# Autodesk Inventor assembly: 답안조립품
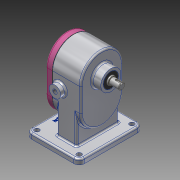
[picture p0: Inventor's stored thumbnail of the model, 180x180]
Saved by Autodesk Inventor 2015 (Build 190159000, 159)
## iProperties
Created: 2020-09
Part Number: 답안조립품
Document SubType Name: Assembly
Designer: LINEART-A501
Author: LINEART-A501
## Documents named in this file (11)
- C:\Users\LINEART-A501\Desktop\700906V1024\답안조립품.iam
- C:\Users\LINEART-A501\Desktop\700906V1024\본체.ipt
- C:\Users\LINEART-A501\Desktop\700906V1024\커버.ipt
- C:\Users\LINEART-A501\Desktop\700906V1024\베어링부시.ipt
- C:\Users\LINEART-A501\Desktop\700906V1024\개스킷.ipt
- C:\Users\LINEART-A501\Desktop\700906V1024\메인축.ipt
- C:\Users\LINEART-A501\Desktop\700906V1024\오일 실 16 28 7.ipt
- C:\Users\LINEART-A501\Desktop\700906V1024\서브축.ipt
- C:\Users\LINEART-A501\Desktop\700906V1024\키 6 x 6 x 18.ipt
- C:\Users\LINEART-A501\Desktop\700906V1024\볼트 M5.ipt
- C:\Users\LINEART-A501\Desktop\700906V1024\스퍼기어.ipt
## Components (1 placed, 1 different names)
1. 개스킷:1
